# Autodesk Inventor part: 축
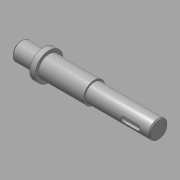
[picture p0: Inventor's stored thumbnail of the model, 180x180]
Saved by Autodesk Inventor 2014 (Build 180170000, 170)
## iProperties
Created: 2015-09
Part Number: 축
Material: 강철, 연강
Document SubType Name: Modeling
Designer: mduedu
Density: 7.86 g/cm^3
Mass: 263.424 g
Surface Area: 86.4309 cm^2
Volume: 33.5145 cm^3
Appearance: Steel
Author: mduedu
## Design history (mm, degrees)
sketch "스케치1"
  geometry: L1 (-64, 0)-(64, 0); L2 (-64, 0)-(-64, 8.5); L3 (-64, 8.5)-(-43, 8.5); L4 (-43, 8.5)-(-43, 13); L5 (-43, 13)-(-38, 13); L6 (-38, 13)-(-38, 10); L7 (-38, 10)-(4, 10); L8 (4, 10)-(4, 8.5); L9 (4, 8.5)-(64, 8.5); L10 (64, 8.5)-(64, 0); 2 further points
  constraints: 20 end point, 5 parallel, 2 horizontal, 2 perpendicular, 1 coincident, 1 midpoint, 1 vertical
  dimensions: "d0" = 128 distance of L1.start L1.end; "d2" = 5 distance of L4.end L5.end; "d3" = 42 distance of L6.end L7.end; "d4" = 60 distance of L8.end L9.end; "d5" = 17 diameter of L3 L1; "d6" = 17 diameter of L9 L1; "d7" = 20 diameter of L7 L1; "d8" = 26 diameter of L5 L1
revolve "회전1" sketch "스케치1" stored, may be unused: angle "d9" = 90 deg
node "작업 평면1"
sketch "스케치2"
  geometry: L1 (5.5, 2.5)-(18.5, 2.5); L2 (18.5, -2.5)-(5.5, -2.5); L3 (5.5, 2.5)-(18.5, -2.5); L4 (18.5, 2.5)-(5.5, -2.5); L5 (30, -8.5)-(30, 8.5) reference; A1 r 2.5 centre (5.5, 0) between (5.5, 2.5) and (5.5, -2.5); A2 r 2.5 centre (18.5, 0) between (18.5, -2.5) and (18.5, 2.5); 2 further points
  constraints: 8 end point, 4 point on circle, 4 tangent, 2 centre point, 2 midpoint, 1 horizontal, 1 horizontal alignment, 1 parallel
  dimensions: "d10" = 18 dimension on A2 A1; "d12" = 9 distance edge to line of A2 L5; "d13" = 5 distance between parallel lines of L2 L1
extrude "돌출1" cut sketch "스케치2" distance "d14" = 3; taper "d15" = 0 deg
node "작업 평면2"
sketch "스케치4"
  geometry: L1 (7, -3)-(-9, -3); L2 (-9, 3)-(7, 3); L3 (-21, 10)-(-21, -10) reference; A1 r 3 centre (-9, 0) between (-9, 3) and (-9, -3); A2 r 3 centre (7, 0) between (7, -3) and (7, 3); 1 further point
  constraints: 4 end point, 4 point on circle, 4 tangent, 2 centre point, 1 horizontal, 1 horizontal alignment, 1 parallel
  dimensions: "d16" = 22 dimension on A1 A2; "d18" = 6 distance between parallel lines of L2 L1; "d19" = 9 distance edge to line of A1 L3
extrude "돌출2" cut sketch "스케치4" distance "d20" = 3.5; taper "d21" = 0 deg
sketch "스케치5"
  geometry: L1 (4, 8.5)-(64, 8.5) reference; L2 (4, -8.5)-(64, -8.5) reference; L3 (37, 8.5)-(37, -8.5); L4 (37, -6.5)-(35, -8.5); L5 (37, -8.5)-(35, -8.5); L6 (37, -8.5)-(37, -6.5); L7 (4, -10)-(4, 10) reference; 1 further point
  constraints: 8 end point, 4 point on line, 1 collinear, 1 perpendicular
  dimensions: "d22" = 4 diameter of L4.end L3; "d24" = 45 deg angle of L3 L4; "d26" = 33 distance between parallel lines of L3 L7
revolve "회전2" sketch "스케치5" stored, may be unused: angle "d27" = 90 deg
chamfer "모따기1" distance "d28" = 1; stored, may be unused: second distance "d29" = 2, angle "d30" = 45 deg
sketch "스케치6"
  geometry: L1 (37, -6.5)-(35, -8.5) reference; L2 (37, -6.5)-(39, -8.5) reference; 2 further points
  constraints: 1 coincident
node "솔리드1"
